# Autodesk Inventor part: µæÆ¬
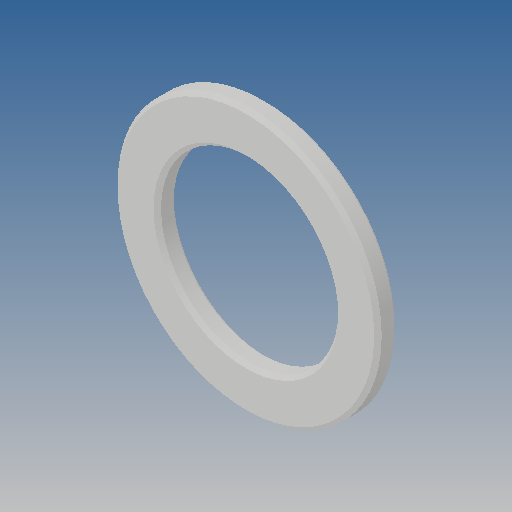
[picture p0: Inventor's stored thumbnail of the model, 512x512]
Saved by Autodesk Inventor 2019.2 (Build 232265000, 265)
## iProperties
Created: 2013-09
Part Number: µæÆ¬
Material: Ogólny
Document SubType Name: Modeling
Designer: CADENGINEERING4
Density: 1 g/cm^3
Appearance: Domyślna
Author: CADENGINEERING4
Revision Number: ÈÎºÎ
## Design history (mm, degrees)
feature "µ¹½Ç2"
node "Bryła1"
